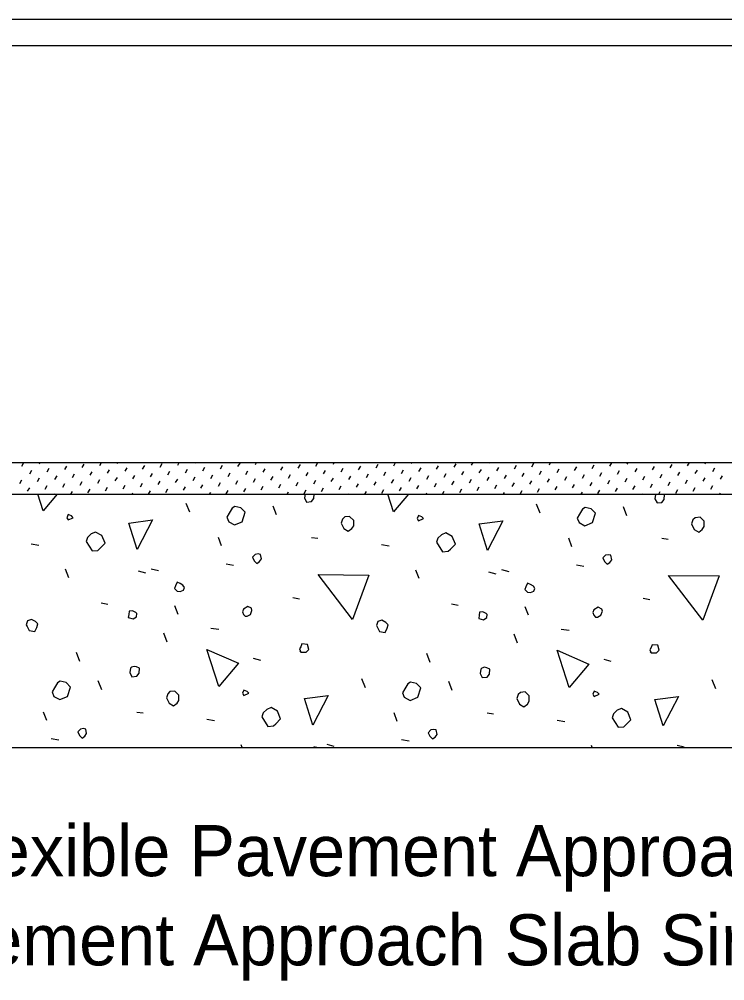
# Model space of a CAD drawing. Extents: x 0 to 41.1, y 0 to 25.9.
# Drawn here: x 26.642 to 29.426, y 9.64 to 13.435 of the extents above; entities that cross this region are included whole.
import ezdxf

# ---------------------------------------------------------------- set-up
doc = ezdxf.new("R2010")
doc.units = 0
for name, color, linetype in [('Dimension', 7, 'Continuous'), ('Miscellaneous', 7, 'Continuous'), ('TrafBarrierConc', 7, 'Continuous')]:
    doc.layers.add(name, color=color, linetype=linetype)

msp = doc.modelspace()

# ---------------------------------------------------------------- linework, layer by layer
at = {"layer": 'Miscellaneous'}
for p, q in [((26.6529, 11.6714), (26.6606, 11.6848)), ((26.6834, 11.6409), (26.6915, 11.6549)), ((26.7221, 11.6796), (26.7251, 11.6848)), ((26.7526, 11.649), (26.7607, 11.663)), ((26.8218, 11.6571), (26.8299, 11.6711)), ((26.8909, 11.6652), (26.899, 11.6792)), ((26.9601, 11.6733), (26.9667, 11.6848)), ((26.9906, 11.6428), (26.9987, 11.6568)), ((27.0293, 11.6814), (27.0312, 11.6848)), ((27.0598, 11.6509), (27.0679, 11.6649)), ((27.129, 11.659), (27.1371, 11.673)), ((27.1981, 11.6671), (27.2062, 11.6811)), ((27.2673, 11.6752), (27.2728, 11.6848)), ((27.2978, 11.6447), (27.3059, 11.6587)), ((27.3365, 11.6833), (27.3373, 11.6848)), ((27.367, 11.6528), (27.3751, 11.6668)), ((27.4361, 11.6609), (27.4442, 11.6749)), ((27.5053, 11.669), (27.5134, 11.683)), ((27.5358, 11.6385), (27.5439, 11.6524)), ((27.5745, 11.6771), (27.5789, 11.6848)), ((27.605, 11.6466), (27.6131, 11.6605)), ((27.6742, 11.6547), (27.6823, 11.6686)), ((27.7433, 11.6628), (27.7514, 11.6768)), ((27.8125, 11.6709), (27.8206, 11.6848)), ((27.843, 11.6403), (27.8511, 11.6543)), ((27.8817, 11.679), (27.885, 11.6848)), ((27.9122, 11.6484), (27.9203, 11.6624)), ((27.9814, 11.6565), (27.9895, 11.6705)), ((28.0505, 11.6646), (28.0586, 11.6786)), ((28.1197, 11.6727), (28.1267, 11.6848)), ((28.1502, 11.6422), (28.1583, 11.6562)), ((28.1888, 11.6808), (28.1911, 11.6848)), ((28.2194, 11.6503), (28.2275, 11.6643)), ((28.2885, 11.6584), (28.2966, 11.6724)), ((28.3577, 11.6665), (28.3658, 11.6805)), ((28.4269, 11.6746), (28.4328, 11.6848)), ((28.4574, 11.6441), (28.4655, 11.6581)), ((28.496, 11.6827), (28.4972, 11.6848)), ((28.5266, 11.6522), (28.5347, 11.6662)), ((28.5957, 11.6603), (28.6038, 11.6743)), ((28.6649, 11.6684), (28.673, 11.6824)), ((28.6954, 11.6379), (28.7035, 11.6519)), ((28.7341, 11.6765), (28.7389, 11.6848)), ((28.7646, 11.646), (28.7727, 11.66)), ((28.8032, 11.6846), (28.8033, 11.6848)), ((28.8337, 11.6541), (28.8419, 11.6681)), ((28.9029, 11.6622), (28.911, 11.6762)), ((28.9721, 11.6703), (28.9802, 11.6843)), ((29.0026, 11.6397), (29.0107, 11.6537)), ((29.0412, 11.6784), (29.045, 11.6848)), ((29.0718, 11.6478), (29.0799, 11.6618)), ((29.1409, 11.6559), (29.149, 11.6699)), ((29.2101, 11.664), (29.2182, 11.678)), ((29.2793, 11.6721), (29.2866, 11.6848)), ((29.3098, 11.6416), (29.3179, 11.6556)), ((29.3484, 11.6803), (29.3511, 11.6848)), ((29.379, 11.6497), (29.3871, 11.6637)), ((26.6448, 11.6023), (26.6529, 11.6163)), ((26.714, 11.6104), (26.7221, 11.6244)), ((26.7831, 11.6185), (26.7912, 11.6325)), ((26.8523, 11.6266), (26.8604, 11.6406)), ((26.9215, 11.6347), (26.9296, 11.6487)), ((26.952, 11.6042), (26.9601, 11.6182)), ((27.0212, 11.6123), (27.0293, 11.6263)), ((27.0903, 11.6204), (27.0984, 11.6344)), ((27.1595, 11.6285), (27.1676, 11.6425)), ((27.2287, 11.6366), (27.2368, 11.6506)), ((27.2592, 11.606), (27.2673, 11.62)), ((27.3283, 11.6141), (27.3365, 11.6281)), ((27.3975, 11.6222), (27.4056, 11.6362)), ((27.4667, 11.6303), (27.4748, 11.6443)), ((27.4972, 11.5998), (27.5053, 11.6138)), ((27.5664, 11.6079), (27.5745, 11.6219)), ((27.6355, 11.616), (27.6436, 11.63)), ((27.7047, 11.6241), (27.7128, 11.6381)), ((27.7739, 11.6322), (27.782, 11.6462)), ((27.8044, 11.6017), (27.8125, 11.6157)), ((27.8736, 11.6098), (27.8817, 11.6238)), ((27.9427, 11.6179), (27.9508, 11.6319)), ((28.0119, 11.626), (28.02, 11.64)), ((28.081, 11.6341), (28.0892, 11.6481)), ((28.1116, 11.6036), (28.1197, 11.6176)), ((28.1807, 11.6117), (28.1888, 11.6257)), ((28.2499, 11.6198), (28.258, 11.6338)), ((28.3191, 11.6279), (28.3272, 11.6419)), ((28.3882, 11.636), (28.3963, 11.65)), ((28.4188, 11.6055), (28.4269, 11.6194)), ((28.4879, 11.6136), (28.496, 11.6275)), ((28.5571, 11.6217), (28.5652, 11.6357)), ((28.6263, 11.6298), (28.6344, 11.6438)), ((28.6568, 11.5992), (28.6649, 11.6132)), ((28.726, 11.6073), (28.7341, 11.6213)), ((28.7951, 11.6154), (28.8032, 11.6294)), ((28.8643, 11.6235), (28.8724, 11.6375)), ((28.9334, 11.6316), (28.9415, 11.6456)), ((28.964, 11.6011), (28.9721, 11.6151)), ((29.0331, 11.6092), (29.0412, 11.6232)), ((29.1023, 11.6173), (29.1104, 11.6313)), ((29.1715, 11.6254), (29.1796, 11.6394)), ((29.2406, 11.6335), (29.2487, 11.6475)), ((29.2712, 11.603), (29.2793, 11.617)), ((29.3403, 11.6111), (29.3484, 11.6251)), ((29.4095, 11.6192), (29.4176, 11.6332)), ((26.6753, 11.5718), (26.6834, 11.5857)), ((26.7445, 11.5799), (26.7526, 11.5939)), ((26.8137, 11.588), (26.8218, 11.602)), ((26.8828, 11.5961), (26.8909, 11.6101)), ((26.9134, 11.5655), (26.9215, 11.5795)), ((26.9825, 11.5736), (26.9906, 11.5876)), ((27.0517, 11.5817), (27.0598, 11.5957)), ((27.1209, 11.5898), (27.129, 11.6038)), ((27.19, 11.5979), (27.1981, 11.6119)), ((27.2206, 11.5674), (27.2287, 11.5814)), ((27.2897, 11.5755), (27.2978, 11.5895)), ((27.3589, 11.5836), (27.367, 11.5976)), ((27.428, 11.5917), (27.4361, 11.6057)), ((27.4586, 11.5612), (27.4667, 11.5752)), ((27.5277, 11.5693), (27.5358, 11.5833)), ((27.5969, 11.5774), (27.605, 11.5914)), ((27.6661, 11.5855), (27.6742, 11.5995)), ((27.7352, 11.5936), (27.7433, 11.6076)), ((27.7658, 11.5631), (27.7739, 11.5771)), ((27.8349, 11.5712), (27.843, 11.5852)), ((27.9041, 11.5793), (27.9122, 11.5933)), ((27.9733, 11.5874), (27.9814, 11.6014)), ((28.0424, 11.5955), (28.0505, 11.6095)), ((28.0729, 11.5649), (28.081, 11.5789)), ((28.1421, 11.573), (28.1502, 11.587)), ((28.2113, 11.5811), (28.2194, 11.5951)), ((28.2804, 11.5892), (28.2885, 11.6032)), ((28.3496, 11.5973), (28.3577, 11.6113)), ((28.3801, 11.5668), (28.3882, 11.5808)), ((28.4493, 11.5749), (28.4574, 11.5889)), ((28.5185, 11.583), (28.5266, 11.597)), ((28.5876, 11.5911), (28.5957, 11.6051)), ((28.6873, 11.5687), (28.6954, 11.5827)), ((28.7565, 11.5768), (28.7646, 11.5908)), ((28.8256, 11.5849), (28.8337, 11.5989)), ((28.8948, 11.593), (28.9029, 11.607)), ((28.9253, 11.5625), (28.9334, 11.5765)), ((28.9945, 11.5706), (29.0026, 11.5846)), ((29.0637, 11.5787), (29.0718, 11.5927)), ((29.1328, 11.5868), (29.1409, 11.6008)), ((29.202, 11.5949), (29.2101, 11.6089)), ((29.2325, 11.5644), (29.2406, 11.5783)), ((29.3017, 11.5725), (29.3098, 11.5864)), ((29.3709, 11.5806), (29.379, 11.5946)), ((26.7811, 11.5598), (26.7831, 11.5633)), ((26.8456, 11.5598), (26.8523, 11.5714)), ((27.0872, 11.5598), (27.0903, 11.5652)), ((27.1517, 11.5598), (27.1595, 11.5733)), ((27.3933, 11.5598), (27.3975, 11.5671)), ((27.6349, 11.5598), (27.6355, 11.5609)), ((27.6994, 11.5598), (27.7047, 11.569)), ((27.941, 11.5598), (27.9427, 11.5627)), ((28.0055, 11.5598), (28.0119, 11.5708)), ((28.2471, 11.5598), (28.2499, 11.5646)), ((28.3116, 11.5598), (28.3191, 11.5727)), ((28.5532, 11.5598), (28.5571, 11.5665)), ((28.6182, 11.5606), (28.6263, 11.5746)), ((28.7948, 11.5598), (28.7951, 11.5603)), ((28.8593, 11.5598), (28.8643, 11.5684)), ((29.1009, 11.5598), (29.1023, 11.5621)), ((29.1654, 11.5598), (29.1715, 11.5702)), ((29.407, 11.5598), (29.4095, 11.564)), ((27.3148, 11.4887), (27.3006, 11.524)), ((27.6577, 11.4781), (27.6436, 11.5134)), ((28.6972, 11.4851), (28.683, 11.5205)), ((29.0401, 11.4745), (29.026, 11.5099)), ((27.4403, 11.3561), (27.4279, 11.3897)), ((27.7956, 11.3897), (27.8204, 11.3861)), ((28.8227, 11.3526), (28.8103, 11.3861)), ((29.178, 11.3861), (29.2028, 11.3826)), ((26.689, 11.3649), (26.7191, 11.3596)), ((28.0714, 11.3614), (28.1014, 11.3561)), ((27.458, 11.2854), (27.488, 11.2801)), ((28.8404, 11.2818), (28.8704, 11.2765)), ((26.8375, 11.2306), (26.8251, 11.2642)), ((27.1115, 11.2571), (27.1398, 11.25)), ((27.1628, 11.2659), (27.191, 11.2589)), ((28.2199, 11.227), (28.2075, 11.2606)), ((28.4939, 11.2536), (28.5222, 11.2465)), ((28.5452, 11.2624), (28.5734, 11.2553)), ((26.9648, 11.1316), (26.9913, 11.1263)), ((27.7214, 11.1528), (27.7479, 11.1475)), ((28.3472, 11.1281), (28.3737, 11.1227)), ((29.1038, 11.1493), (29.1303, 11.144)), ((27.2688, 11.0856), (27.2565, 11.1192)), ((28.6512, 11.0821), (28.6388, 11.1157)), ((27.2264, 10.976), (27.2123, 11.0114)), ((27.3979, 11.0308), (27.4297, 11.0273)), ((28.6088, 10.9725), (28.5947, 11.0078)), ((28.7803, 11.0273), (28.8121, 11.0238)), ((26.8817, 10.9), (26.8675, 10.9354)), ((28.2641, 10.8965), (28.2499, 10.9318)), ((27.5658, 10.9124), (27.5941, 10.9053)), ((28.9482, 10.9089), (28.9765, 10.9018)), ((26.9683, 10.7886), (26.9542, 10.824)), ((28.0078, 10.7957), (27.9936, 10.8311)), ((28.3507, 10.7851), (28.3366, 10.8205)), ((29.3901, 10.7922), (29.376, 10.8275)), ((26.7509, 10.6667), (26.7385, 10.7003)), ((27.1062, 10.7003), (27.1309, 10.6967)), ((27.382, 10.672), (27.412, 10.6667)), ((28.1333, 10.6631), (28.1209, 10.6967)), ((28.4886, 10.6967), (28.5133, 10.6932)), ((28.7644, 10.6684), (28.7944, 10.6631)), ((26.7685, 10.596), (26.7986, 10.5907)), ((28.1509, 10.5924), (28.181, 10.5871)), ((27.5223, 10.5598), (27.5181, 10.5712)), ((27.8045, 10.5641), (27.8218, 10.5598)), ((27.8557, 10.573), (27.884, 10.5659)), ((28.9034, 10.5598), (28.9005, 10.5677)), ((29.1869, 10.5606), (29.1901, 10.5598)), ((29.2381, 10.5694), (29.2664, 10.5624))]:
    msp.add_line(p, q, dxfattribs=at)
for points in [[(26.7367, 11.494), (26.7153, 11.5598)], [(26.7924, 11.5598), (26.7367, 11.494)], [(27.7673, 11.5452), (27.7762, 11.5293), (27.7956, 11.5311), (27.8045, 11.5435), (27.8059, 11.5598)], [(27.7702, 11.5598), (27.7673, 11.5452)], [(28.1191, 11.4904), (28.0966, 11.5598)], [(28.1778, 11.5598), (28.1191, 11.4904)], [(29.1497, 11.5417), (29.1586, 11.5258), (29.178, 11.5276), (29.1869, 11.5399), (29.1886, 11.5594), (29.1877, 11.5598)], [(29.1537, 11.5598), (29.1533, 11.5594), (29.1497, 11.5417)], [(27.4686, 11.4516), (27.4916, 11.4392), (27.5216, 11.4516), (27.534, 11.4887), (27.5163, 11.5064), (27.4933, 11.5117), (27.4827, 11.5046), (27.4704, 11.4851), (27.4615, 11.4692), (27.4686, 11.4516)], [(28.851, 11.448), (28.874, 11.4356), (28.904, 11.448), (28.9164, 11.4851), (28.8987, 11.5028), (28.8757, 11.5081), (28.8651, 11.5011), (28.8527, 11.4816), (28.8439, 11.4657), (28.851, 11.448)], [(26.8357, 11.4586), (26.8552, 11.4675), (26.8481, 11.4745), (26.8357, 11.4798), (26.8304, 11.4675), (26.8357, 11.4586)], [(27.9123, 11.4463), (27.9229, 11.425), (27.9406, 11.4144), (27.9547, 11.425), (27.9618, 11.4356), (27.9618, 11.4569), (27.9459, 11.4728), (27.9264, 11.471), (27.9176, 11.4622), (27.9123, 11.4463)], [(28.2181, 11.4551), (28.2376, 11.4639), (28.2305, 11.471), (28.2181, 11.4763), (28.2128, 11.4639), (28.2181, 11.4551)], [(29.2947, 11.4427), (29.3053, 11.4215), (29.323, 11.4109), (29.3371, 11.4215), (29.3442, 11.4321), (29.3442, 11.4533), (29.3283, 11.4692), (29.3088, 11.4675), (29.3, 11.4586), (29.2947, 11.4427)], [(27.108, 11.342), (27.0744, 11.4463), (27.1681, 11.4586), (27.108, 11.342)], [(28.4904, 11.3384), (28.4568, 11.4427), (28.5505, 11.4551), (28.4904, 11.3384)], [(26.9064, 11.3738), (26.9294, 11.3366), (26.9524, 11.3384), (26.9612, 11.3473), (26.9807, 11.3667), (26.9683, 11.3968), (26.9436, 11.4109), (26.9259, 11.4038), (26.9117, 11.3897), (26.9064, 11.3738)], [(28.2888, 11.3702), (28.3118, 11.3331), (28.3348, 11.3349), (28.3436, 11.3437), (28.3631, 11.3632), (28.3507, 11.3932), (28.326, 11.4074), (28.3083, 11.4003), (28.2941, 11.3861), (28.2888, 11.3702)], [(27.5693, 11.2978), (27.58, 11.2872), (27.5906, 11.2942), (27.5976, 11.3048), (27.5941, 11.3225), (27.5853, 11.3243), (27.5729, 11.3225), (27.5623, 11.3119), (27.5693, 11.2978)], [(28.9517, 11.2942), (28.9623, 11.2836), (28.973, 11.2907), (28.98, 11.3013), (28.9765, 11.319), (28.9677, 11.3207), (28.9553, 11.319), (28.9447, 11.3084), (28.9517, 11.2942)], [(27.9565, 11.0662), (27.8221, 11.243), (28.0219, 11.2412), (27.9565, 11.0662)], [(29.3389, 11.0626), (29.2045, 11.2394), (29.4043, 11.2377), (29.3389, 11.0626)], [(27.2653, 11.1776), (27.2777, 11.1758), (27.29, 11.1811), (27.2936, 11.1917), (27.2883, 11.2005), (27.2777, 11.2076), (27.2653, 11.2129), (27.2582, 11.1988), (27.2547, 11.1882), (27.2653, 11.1776)], [(28.6477, 11.174), (28.6601, 11.1722), (28.6724, 11.1776), (28.676, 11.1882), (28.6707, 11.197), (28.6601, 11.2041), (28.6477, 11.2094), (28.6406, 11.1952), (28.6371, 11.1846), (28.6477, 11.174)], [(27.0726, 11.0733), (27.0921, 11.0679), (27.1044, 11.0768), (27.1062, 11.0892), (27.1027, 11.0927), (27.0885, 11.0998), (27.0761, 11.098), (27.0744, 11.0856), (27.0726, 11.0733)], [(27.534, 11.0786), (27.5411, 11.0786), (27.5552, 11.0856), (27.5605, 11.1015), (27.5587, 11.1104), (27.5446, 11.1174), (27.5269, 11.1068), (27.5234, 11.0962), (27.5269, 11.0856), (27.534, 11.0786)], [(28.455, 11.0697), (28.4744, 11.0644), (28.4868, 11.0733), (28.4886, 11.0856), (28.4851, 11.0892), (28.4709, 11.0962), (28.4585, 11.0945), (28.4568, 11.0821), (28.455, 11.0697)], [(28.9164, 11.075), (28.9235, 11.075), (28.9376, 11.0821), (28.9429, 11.098), (28.9411, 11.1068), (28.927, 11.1139), (28.9093, 11.1033), (28.9058, 11.0927), (28.9093, 11.0821), (28.9164, 11.075)], [(26.6731, 11.0379), (26.6819, 11.022), (26.7031, 11.0185), (26.712, 11.0344), (26.7155, 11.0485), (26.7067, 11.0573), (26.6908, 11.0662), (26.6749, 11.0609), (26.6696, 11.045), (26.6731, 11.0379)], [(28.0555, 11.0344), (28.0643, 11.0185), (28.0855, 11.0149), (28.0944, 11.0308), (28.0979, 11.045), (28.0891, 11.0538), (28.0732, 11.0626), (28.0573, 11.0573), (28.0519, 11.0414), (28.0555, 11.0344)], [(27.7532, 10.9371), (27.7744, 10.9371), (27.785, 10.9477), (27.7797, 10.9672), (27.7567, 10.969), (27.7532, 10.9583), (27.7479, 10.9495), (27.7532, 10.9371), (27.7497, 10.9407)], [(27.4297, 10.801), (27.382, 10.9477), (27.5075, 10.8929), (27.4297, 10.801)], [(28.8121, 10.7975), (28.7644, 10.9442), (28.8899, 10.8894), (28.8121, 10.7975)], [(29.1356, 10.9336), (29.1568, 10.9336), (29.1674, 10.9442), (29.1621, 10.9637), (29.1391, 10.9654), (29.1356, 10.9548), (29.1303, 10.946), (29.1356, 10.9336), (29.1321, 10.9371)], [(27.0779, 10.8558), (27.0867, 10.8399), (27.1062, 10.8417), (27.115, 10.854), (27.1168, 10.8735), (27.1044, 10.8788), (27.0956, 10.8806), (27.085, 10.877), (27.0814, 10.8735), (27.0779, 10.8558)], [(28.4603, 10.8523), (28.4691, 10.8364), (28.4886, 10.8381), (28.4974, 10.8505), (28.4992, 10.87), (28.4868, 10.8753), (28.478, 10.877), (28.4674, 10.8735), (28.4638, 10.87), (28.4603, 10.8523)], [(26.7792, 10.7621), (26.8021, 10.7498), (26.8322, 10.7621), (26.8446, 10.7992), (26.8269, 10.8169), (26.8039, 10.8222), (26.7933, 10.8152), (26.7809, 10.7957), (26.7721, 10.7798), (26.7792, 10.7621)], [(28.1616, 10.7586), (28.1845, 10.7462), (28.2146, 10.7586), (28.227, 10.7957), (28.2093, 10.8134), (28.1863, 10.8187), (28.1757, 10.8116), (28.1633, 10.7922), (28.1545, 10.7763), (28.1616, 10.7586)], [(27.2229, 10.7568), (27.2335, 10.7356), (27.2512, 10.725), (27.2653, 10.7356), (27.2724, 10.7462), (27.2724, 10.7674), (27.2565, 10.7833), (27.237, 10.7816), (27.2282, 10.7727), (27.2229, 10.7568)], [(27.5287, 10.7657), (27.5481, 10.7745), (27.5411, 10.7816), (27.5287, 10.7869), (27.5234, 10.7745), (27.5287, 10.7657)], [(28.6053, 10.7533), (28.6159, 10.7321), (28.6335, 10.7215), (28.6477, 10.7321), (28.6548, 10.7427), (28.6548, 10.7639), (28.6388, 10.7798), (28.6194, 10.778), (28.6106, 10.7692), (28.6053, 10.7533)], [(28.9111, 10.7621), (28.9305, 10.771), (28.9235, 10.778), (28.9111, 10.7833), (28.9058, 10.771), (28.9111, 10.7621)], [(27.8009, 10.649), (27.7673, 10.7533), (27.861, 10.7657), (27.8009, 10.649)], [(29.1833, 10.6455), (29.1497, 10.7498), (29.2434, 10.7621), (29.1833, 10.6455)], [(27.5994, 10.6808), (27.6224, 10.6437), (27.6454, 10.6455), (27.6542, 10.6543), (27.6736, 10.6737), (27.6613, 10.7038), (27.6365, 10.7179), (27.6188, 10.7109), (27.6047, 10.6967), (27.5994, 10.6808)], [(28.9818, 10.6773), (29.0048, 10.6401), (29.0278, 10.6419), (29.0366, 10.6508), (29.056, 10.6702), (29.0437, 10.7003), (29.0189, 10.7144), (29.0012, 10.7073), (28.9871, 10.6932), (28.9818, 10.6773)], [(26.8799, 10.6083), (26.8905, 10.5977), (26.9011, 10.6048), (26.9082, 10.6154), (26.9047, 10.6331), (26.8958, 10.6348), (26.8835, 10.6331), (26.8728, 10.6225), (26.8799, 10.6083)], [(28.2623, 10.6048), (28.2729, 10.5942), (28.2835, 10.6013), (28.2906, 10.6119), (28.2871, 10.6295), (28.2782, 10.6313), (28.2658, 10.6295), (28.2552, 10.6189), (28.2623, 10.6048)]]:
    msp.add_lwpolyline(points, dxfattribs=at)
at = {"layer": 'TrafBarrierConc'}
for p, q in [((23.987, 13.4349), (37.3177, 13.4349)), ((23.987, 13.3307), (37.3177, 13.3307)), ((23.987, 11.6848), (39.8181, 11.6848)), ((23.987, 11.5598), (39.8181, 11.5598)), ((23.987, 10.5598), (39.8181, 10.5598))]:
    msp.add_line(p, q, dxfattribs=at)

# ---------------------------------------------------------------- texts
at = {"layer": 'Dimension'}
for s, p in [('Approach Slab (Flexible Pavement Approach Slab ', (24.3764, 10.0525)), ('Shown, Rigid Pavement Approach Slab Similar)', (24.3764, 9.7005))]:
    msp.add_text(s, height=0.2016, dxfattribs=at).set_placement(p)

doc.saveas('drawing.dxf')
